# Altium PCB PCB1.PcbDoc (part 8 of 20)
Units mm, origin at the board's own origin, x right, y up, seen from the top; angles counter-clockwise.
Board outline 294.51 x 138.18 mm, 12 copper layers (Top Layer 1 _Signal, L2_GND, L3_Signals, L4_GND, L5_POWER, L6_Signals, L7_GND, L8_Signals, L9_GND, L10_POWER, L11_GND, Bottom Layer_Signals), stack 1.788 mm thick; 1254 components, 836 nets, 5699 pads, 2073 vias.
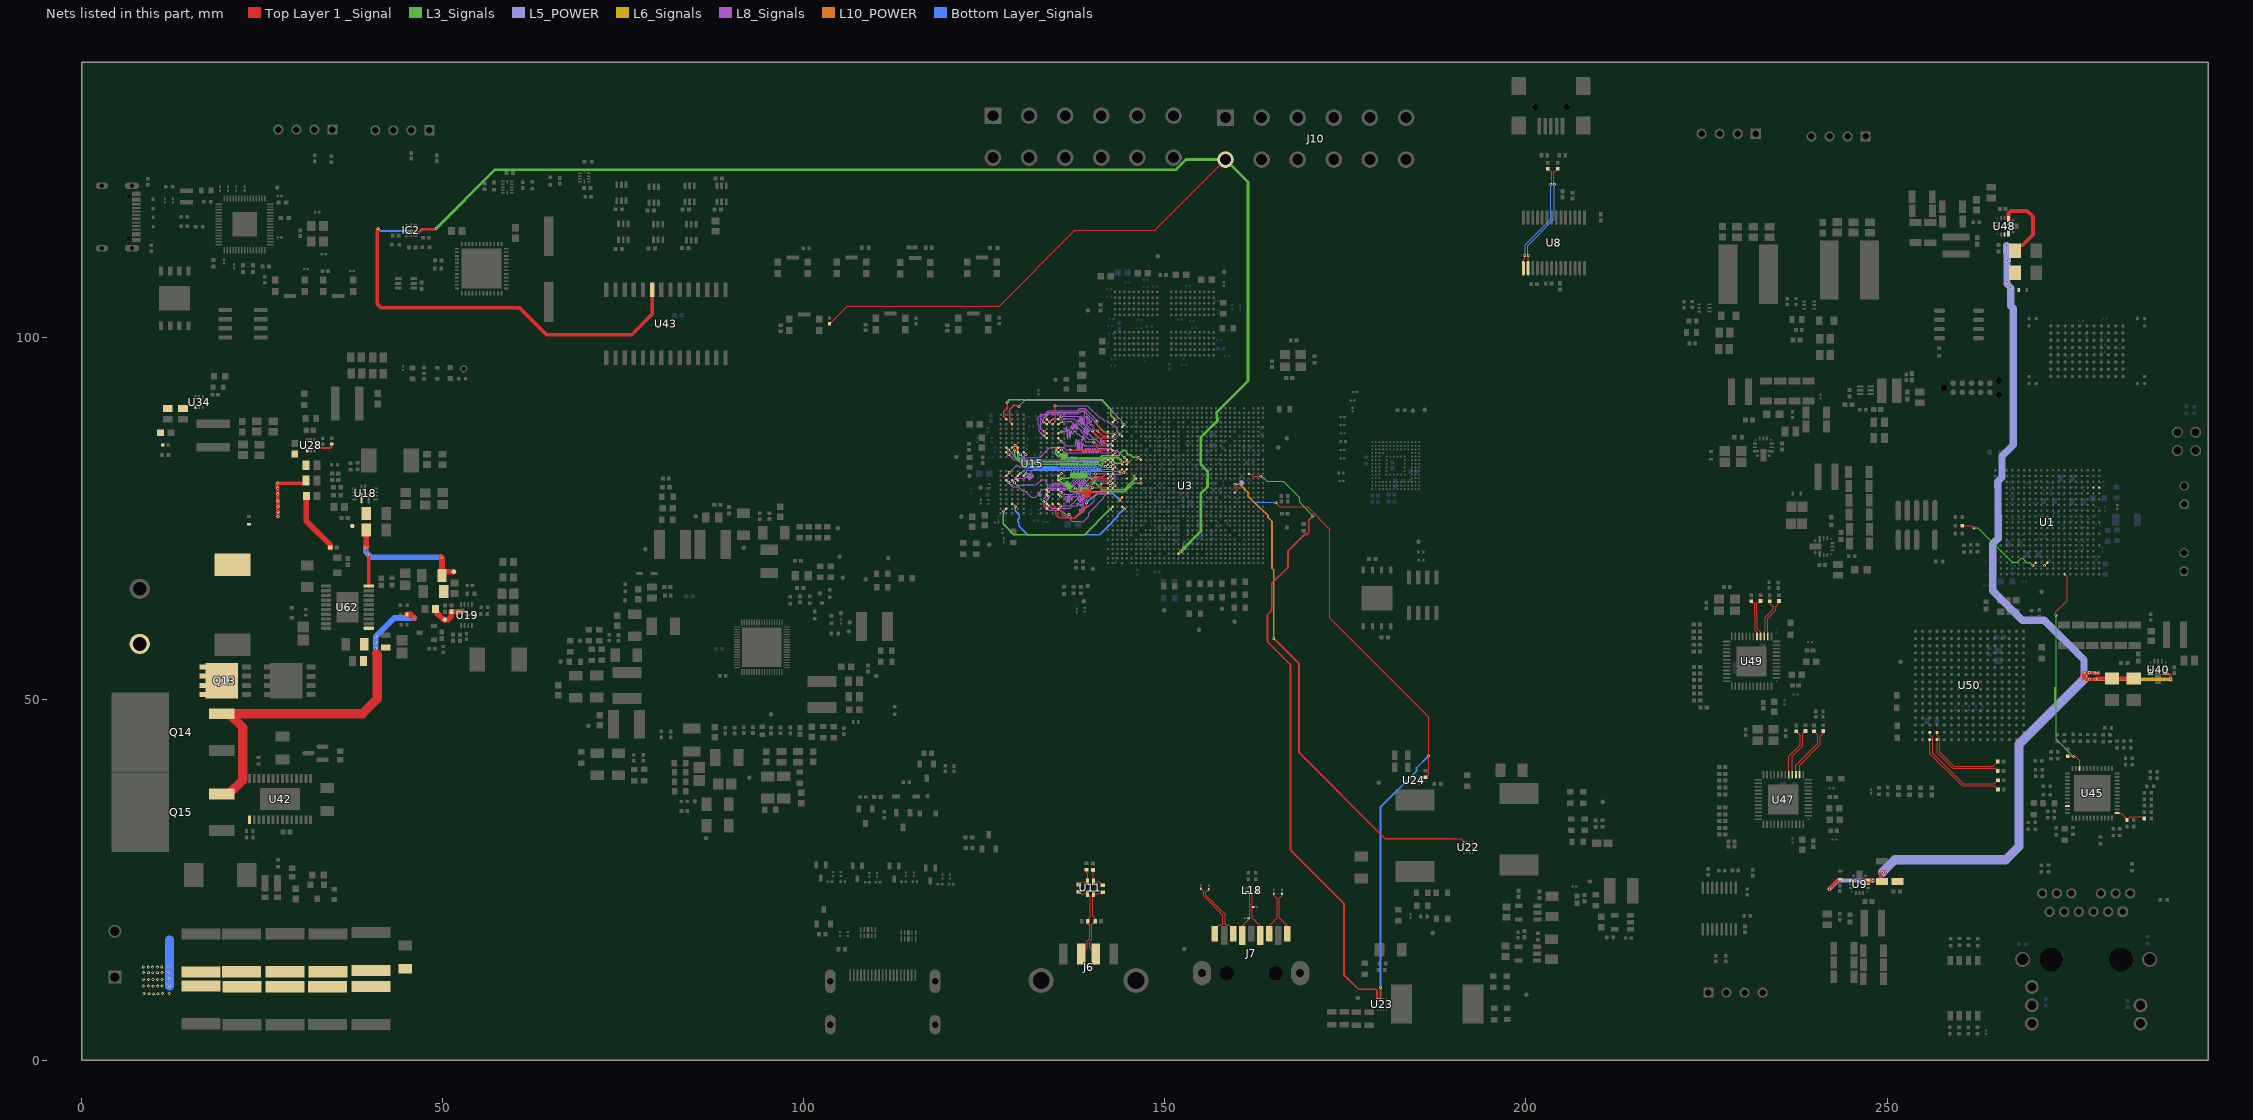
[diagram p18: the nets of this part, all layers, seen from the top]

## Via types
v1: diameter 0.4, hole 0.2, Top Layer 1 _Signal to Bottom Layer_Signals, 2009 vias
v2: diameter 0.508, hole 0.254, Top Layer 1 _Signal to Bottom Layer_Signals, 36 vias
v3: diameter 0.5, hole 0.2, Top Layer 1 _Signal to Bottom Layer_Signals, 12 vias
v4: diameter 1.27, hole 0.711, Top Layer 1 _Signal to Bottom Layer_Signals, 6 vias
v5: diameter 0.3, hole 0.2, Top Layer 1 _Signal to Bottom Layer_Signals, 5 vias
v6: diameter 0.254, hole 0.2, Top Layer 1 _Signal to Bottom Layer_Signals, 3 vias
v7: diameter 0.305, hole 0.2, Top Layer 1 _Signal to Bottom Layer_Signals, 1 vias
v8: diameter 0.254, hole 0.152, Top Layer 1 _Signal to Bottom Layer_Signals, 1 vias

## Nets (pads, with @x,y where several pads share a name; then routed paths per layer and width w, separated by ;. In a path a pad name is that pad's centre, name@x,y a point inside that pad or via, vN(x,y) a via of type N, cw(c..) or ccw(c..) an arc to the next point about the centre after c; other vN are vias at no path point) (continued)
12V: 1.2 2.2 3.2 4.2 C20.1 C21.1 C22.1 C184.2 C185.2 C187.1 C188.1 C189.1 C198.2 C321.1 C326.1 C329.1 C435.2 C492.1 C528.1 C529.2 C530.2 L29.2 R55.2 R81.2 R146.2 R296.2 TP16.1 TP65.1 TP66.1 U9.7 U9.8 U9.12 U18.1 U19.1 U28.1 U34.1 U40.7 U40.8 U40.12 U48.7 U48.8 U48.12 U62.10 | length 210.3
  Top Layer 1 _Signal w0.254: U28.1@31.237,84.371 31.26,84.394 31.26,84.592 31.5,84.832 32.474,84.832 32.563,84.743 34.435,84.743 34.635,84.944 R55.2@34.635,85.305
  Top Layer 1 _Signal w0.3: U40.12@288.553,53.474 288.578,53.449 289.093,53.449 289.268,53.274 289.268,53.215 289.282,53.202 v1(289.282,52.71)
  Top Layer 1 _Signal w0.508: v1(27.207,75.285) 27.184,75.308 v1(27.184,75.9) 27.184,76.645 v1(27.199,76.66) 27.207,76.667 v1(27.207,77.458) 27.165,77.499 v1(27.165,78.374) 27.151,78.388 v1(27.151,79.202) 27.136,79.217 v1(27.136,79.898) 30.866,79.898 31.087,80.119 C326.1@31.087,80.272 ; U62.10@39.768,65.636 39.768,69.729 ; v1(242.032,23.677) 242.032,23.792 243.225,24.986 243.49,24.986 243.522,25.018 C187.1@243.522,25.054 ; U9.8@247.213,24.888 247.235,24.867 v1(248.064,24.867) ; C188.1@249.309,24.727 249.143,24.892 249.143,25.805 v1(249.355,26.017) v1(249.901,26.017) ; U48.12@266.819,116.49 266.819,117.235 267.162,117.578 269.41,117.578 270.202,116.786 270.202,114.297 268.742,112.837 268.285,112.837 267.712,112.264 C530.2@267.712,112.089 ; v1(279.304,53.603) 279.288,53.588 v1(278.785,53.588) 278.722,53.651 v1(277.999,53.651) 277.942,53.593 v1(277.256,53.593) 277.256,52.734 v1(277.271,52.718) 277.287,52.734 v1(277.994,52.734) v1(278.927,52.734) 279.036,52.843 C185.2@284.186,52.843
  Top Layer 1 _Signal w0.762: C435.2@31.124,78.123 31.124,74.617 34.444,71.297 R296.2@34.444,70.966 ; v1(39.406,70.945) 1.2@39.406,73.389 ; C198.2@49.015,62.464 49.109,62.37 49.109,62.014 50.13,60.993 50.762,60.993 51.208,61.44 R81.2@51.208,62.094 52.699,62.094 U19.1@52.738,62.133 ; v1(49.819,69.618) 49.905,69.533 4.2@49.905,67.089 49.905,67.339 50.174,67.608 51.519,67.608 TP16.1@51.546,67.634
  L5_POWER w0.508: v1(242.032,23.677) 243.222,24.867 v1(248.064,24.867)
  L5_POWER w1.016: v1(266.532,111.871) 266.559,111.898 v1(266.559,112.753) 266.662,112.651 v1(266.662,110.674) 266.614,110.626 v1(266.614,107.759) 266.614,107.465 v1(267.154,106.925) 267.136,106.907 267.136,104.419 267.455,104.1 267.455,85.171 265.913,83.63 265.913,80.701 265.339,80.126 265.339,79.47 265.358,79.451 265.358,75.39 265.388,75.36 265.388,73.24 265.392,73.235 265.392,72.241 264.66,71.509 264.66,64.978 268.72,60.918 271.776,60.918 277.271,55.423 v1(277.271,52.718)
  L5_POWER w1.27: v1(249.355,26.017) 251.081,27.743 266.439,27.743 268.261,29.565 268.261,43.708 v1(277.271,52.718)
  L6_Signals w0.508: v1(278.927,52.734) 289.258,52.734 v1(289.282,52.71)
  Bottom Layer_Signals w0.762: 39.463,71.167 39.374,71.078 39.374,70.368 40.123,69.618 v1(49.819,69.618)
  other v1: 39.576,69.972
+24V: C39.1 C40.1 C575.2 C576.2 C577.2 C578.2 C579.2 C580.2 C581.2 C582.2 C583.2 C584.2 C585.2 CN1.2 Q13.5 Q13.6 Q13.7 Q13.8 Q14.3 Q15.3 R294.2 R295.2 U42.1 U62.1 | length 58.9
  Top Layer 1 _Signal w0.8: R295.2@45.053,61.694 45.568,61.694 v1(46.028,61.233)
  Top Layer 1 _Signal w1.27: Q15.3@19.417,36.857 20.417,36.857 22.304,38.744 22.304,46.07 20.417,47.956 Q14.3@19.417,47.956 38.884,47.956 40.941,50.014 40.941,56.136 40.816,56.262
  Bottom Layer_Signals w0.8: v1(40.741,56.979) v1(40.741,57.834) v1(40.741,58.667) 43.307,61.233 v1(46.028,61.233)
  Bottom Layer_Signals w1.27: v1(12.157,10.281) 12.157,16.611
  other v1: 9.329,9.181 9.938,9.177 8.63,9.203 10.581,9.19 11.19,9.199 12.198,9.224 9.288,10.238 9.897,10.234 10.54,10.247 8.589,10.259 11.149,10.255 9.877,11.162 8.569,11.187 9.268,11.166 10.52,11.174 11.129,11.183 12.137,11.209 9.247,12.094 9.856,12.089 10.5,12.102 8.548,12.115 11.109,12.111 12.117,12.137 9.234,12.879 9.843,12.875 10.486,12.888 8.535,12.901 11.095,12.897 12.103,12.922
_FIBRI0_N: C593.2 U47.14 | length 7.4
  Top Layer 1 _Signal w0.111: U47.14@237.887,39.535 237.887,40.845 240.775,43.733 240.775,44.842 241.181,45.248 C593.2@241.181,45.563
_FIBRI0_P: C594.2 U47.15 | length 7.5
  Top Layer 1 _Signal w0.111: U47.15@237.388,39.535 237.388,40.825 240.436,43.874 240.436,45.011 C594.2@239.897,45.55
_FIBRI1_N: C607.2 U49.14 | length 5.6
  Top Layer 1 _Signal w0.111: U49.14@233.491,58.655 233.491,59.239 233.486,59.244 233.486,61.187 234.559,62.261 234.559,62.78 235.032,63.252 C607.2@235.032,63.568
_FIBRI1_P: C608.2 U49.15 | length 5.6
  Top Layer 1 _Signal w0.111: U49.15@232.991,58.655 232.991,59.239 233.146,59.395 233.146,61.328 234.22,62.402 234.22,62.76 233.748,63.233 C608.2@233.748,63.548
_FIBRO0_N: C596.2 U47.17 | length 6.9
  Top Layer 1 _Signal w0.111: U47.17@236.388,39.535 236.388,42.058 238.003,43.674 238.003,44.983 237.493,45.494 237.485,45.494 C596.2@237.429,45.55
_FIBRO0_P: C595.2 U47.16 | length 6.8
  Top Layer 1 _Signal w0.111: U47.16@236.887,39.535 236.887,42.078 238.343,43.533 238.343,45.204 C595.2@238.705,45.566
_FIBRO1_N: C610.2 U49.17 | length 5.4
  Top Layer 1 _Signal w0.111: C610.2@231.188,63.549 231.382,63.356 231.634,63.356 231.699,63.291 231.699,61.585 231.757,61.526 231.757,59.473 231.991,59.239 U49.17@231.991,58.655
_FIBRO1_P: C609.2 U49.16 | length 5.5
  Top Layer 1 _Signal w0.111: C609.2@232.468,63.56 232.263,63.356 232.027,63.356 231.962,63.291 231.962,61.694 232.02,61.635 232.02,59.71 232.491,59.239 U49.16@232.491,58.655
_RD0_VS_N: C634.1 U50.P16 | length 13.4
  Top Layer 1 _Signal w0.161: U50.P16@255.919,44.379 255.922,44.376 255.922,42.448 260.411,37.959 264.871,37.959 C634.1@265.348,37.482
_RD0_VS_P: C633.1 U50.P15 | length 14
  Top Layer 1 _Signal w0.161: U50.P15@255.919,45.379 255.919,45.081 256.331,44.669 256.331,42.483 260.541,38.273 264.871,38.273 C633.1@265.348,38.75
_TD0_VS_N: C631.1 U50.N16 | length 11.3
  Top Layer 1 _Signal w0.161: U50.N16@256.919,44.379 256.972,44.327 256.972,44.164 256.988,44.147 256.988,42.515 257.08,42.423 259.101,40.402 264.958,40.402 C631.1@265.342,40.018
_TD0_VS_P: C630.1 U50.N15 | length 12
  Top Layer 1 _Signal w0.161: U50.N15@256.919,45.379 256.919,44.92 257.302,44.538 257.302,42.645 259.231,40.715 264.709,40.715 C630.1@265.326,41.332
_TYPEC0_OTG_D_N: J7.2 L18.2 R92.2 | length 6.9
  Top Layer 1 _Signal w0.131: J7.2@160.691,17.262 160.691,18.627 161.662,19.599 161.786,19.723 161.786,20.481 161.786,20.798 161.8,20.798 161.8,20.955 161.761,20.955 161.761,21.112 161.812,21.112 161.812,21.268 161.761,21.268 161.761,21.425 161.812,21.425 161.812,21.582 161.786,21.582 161.786,21.647 161.786,23.01 161.595,23.201 161.507,23.201 L18.2@161.441,23.267
_TYPEC0_OTG_D_P: J7.3 L18.3 R95.2 | length 6.9
  Top Layer 1 _Signal w0.131: L18.3@162.666,23.267 162.601,23.201 162.287,23.201 162.096,23.01 162.096,19.723 163.191,18.627 J7.3@163.191,17.262
_TYPEC0_SSRX1_N: J7.5 R96.2 | length 6.2
  Top Layer 1 _Signal w0.131: R96.2@166.233,23.047 166.233,22.805 165.846,22.417 165.846,19.723 166.941,18.627 J7.5@166.941,17.487
_TYPEC0_SSRX1_P: J7.6 R97.2 | length 6.2
  Top Layer 1 _Signal w0.131: J7.6@164.441,17.487 164.441,18.627 165.536,19.723 165.536,22.353 165.076,22.813 R97.2@165.076,23.056
_TYPEC0_SSTX1_N: C457.2 J7.8 | length 8.2
  Top Layer 1 _Signal w0.131: C457.2@156.081,23.673 155.677,23.269 155.677,22.852 156.312,22.217 156.358,22.171 157.216,21.313 157.231,21.327 157.341,21.216 157.309,21.184 157.42,21.073 157.438,21.091 157.484,21.045 158.345,20.184 158.345,18.788 158.422,18.711 158.841,18.711 159.441,18.112 J7.8@159.441,17.487
_TYPEC0_SSTX1_P: C458.2 J7.9 | length 8.2
  Top Layer 1 _Signal w0.131: C458.2@154.964,23.719 155.368,23.315 155.368,22.724 158.036,20.056 158.036,18.788 157.959,18.711 157.54,18.711 156.941,18.112 J7.9@156.941,17.487
_TYPEC1_OTG__D_N: J6.2 R74.2 U11.2 U13.2 | length 10.6
  Top Layer 1 _Signal w0.131: R74.2@138.098,23.312 138.148,23.312 138.431,23.029 U11.2@139.302,23.029 139.685,22.646 139.685,22.206 139.685,19.847 139.474,19.636 139.474,19.391 U13.2@139.314,19.231 139.314,18.865 139.601,18.578 139.601,16.791 139.272,16.462 139.272,15.542 J6.2@138.427,14.697
_TYPEC1_OTG__D_P: J6.3 R175.2 U11.3 U14.2 | length 10.6
  Top Layer 1 _Signal w0.131: J6.3@140.427,14.697 139.581,15.542 139.581,16.334 139.91,16.663 139.91,18.768 U14.2@140.365,19.222 140.365,19.588 139.994,19.959 139.994,22.405 140.048,22.459 140.048,22.974 U11.3@140.102,23.029 141.175,23.029 141.368,23.221 R175.2@141.418,23.221
_TYPEC1_OTG_D_N: R74.1 R173.2 U11.1 | length 3.1
  Top Layer 1 _Signal w0.131: R74.1@138.098,24.312 138.148,24.312 138.565,24.729 U11.1@139.302,24.729 139.302,25.857 139.133,26.026 R173.2@139.133,26.342
_TYPEC1_OTG_D_P: R174.2 R175.1 U11.4 | length 3.1
  Top Layer 1 _Signal w0.131: R174.2@140.079,26.325 140.079,25.268 140.102,25.244 U11.4@140.102,24.729 140.861,24.729 141.368,24.221 R175.1@141.418,24.221
_USB__N: R166.1 U8.16 | length 15.6
  Top Layer 1 _Signal w0.161: U8.16@200.291,109.664 200.291,111.398 v1(200.322,111.428) ; v1(203.94,121.278) 203.855,121.363 203.855,122.91 R166.1@204.376,123.43
  Bottom Layer_Signals w0.161: v1(200.322,111.428) 200.237,111.513 200.237,112.769 203.94,116.472 v1(203.94,121.278)
_USB__P: R167.1 U8.15 | length 15.6
  Top Layer 1 _Signal w0.161: U8.15@199.641,109.664 199.641,110.744 199.838,110.941 v1(199.838,111.428) ; R167.1@203.02,123.45 203.541,122.93 203.541,121.363 v1(203.456,121.278)
  Bottom Layer_Signals w0.161: v1(199.838,111.428) 199.923,111.513 199.923,112.899 203.456,116.432 v1(203.456,121.278)
ALLPHYAD: R393.1 R394.2 U45.13 | length 4.6
  Top Layer 1 _Signal w0.152: U45.13@281.874,34.203 282.426,34.203 283.076,33.554 283.076,33.388 R393.1@283.225,33.239 283.225,33.255 283.684,33.715 285.402,33.715 285.642,33.474 R394.2@285.642,33.459
BIG/NPU_EN: R122.1 R123.2 U23.A2 U24.A2 | length 93.1
  Top Layer 1 _Signal w0.161: v1(165.373,77.183) 165.923,76.633 169.756,76.633 172.85,73.538 172.85,61.157 186.52,47.487 186.52,42.123 v1(186.483,42.086) 186.52,42.048 186.52,39.595 186.106,39.18 185.564,39.18 185.449,39.066 185.366,39.066 185.258,38.957 U24.A2@185.247,38.957
  Top Layer 1 _Signal w0.254: U23.A2@179.853,8.514 v1(179.853,10.065)
  Bottom Layer_Signals w0.161: R122.1@160.596,79.938 160.439,79.781 160.439,79.756 160.719,79.475 160.719,79.301 160.763,79.257 160.817,79.257 161.531,78.542 161.531,78.024 162.246,77.31 162.36,77.31 162.431,77.239 165.317,77.239 v1(165.373,77.183)
  Bottom Layer_Signals w0.254: v1(179.853,10.065) 179.853,35.016 184.848,40.011 184.848,40.452 v1(186.483,42.086)
BOOT_SARADC_IN0: IC2.10 U43.23 | length 60.3
  Top Layer 1 _Signal w0.254: IC2.10@45.042,114.493 45.069,114.52 45.371,114.52 45.569,114.718 45.572,114.718 v1(45.667,114.813)
  Top Layer 1 _Signal w0.508: v1(41.027,115.112) 41.027,115.029 40.961,114.963 40.961,104.684 41.47,104.175 60.639,104.175 64.361,100.453 76.18,100.453 78.998,103.272 U43.23@78.998,106.647
  Bottom Layer_Signals w0.254: v1(41.027,115.112) 41.066,115.112 41.365,114.813 v1(45.667,114.813)
BOOT_SARADC_IN0_: IC2.2 J10.7 R130.2 R183.1 U3.AM16 | length 242
  Top Layer 1 _Signal w0.132: R183.1@103.568,101.959 103.572,101.959 106.029,104.416 127.065,104.416 137.538,114.888 148.58,114.888 J10.7@158.395,124.704
  Top Layer 1 _Signal w0.381: IC2.2@46.242,114.493 46.268,114.519 46.606,114.519 47.142,115.055 49.026,115.055 v1(49.105,115.134) ; U3.AM16@151.879,70.128 151.897,70.128 152.222,70.453 v1(152.227,70.453)
  L3_Signals w0.381: v1(49.105,115.134) 57.272,123.301 151.541,123.301 152.944,124.704 J10.7@158.395,124.704 161.5,121.599 161.5,94.025 157.199,89.725 157.199,89.014 157.285,88.928 157.285,88.535 155.628,86.879 155.606,86.879 154.988,86.26 154.988,85.867 154.979,85.859 154.979,82.45 155.931,81.498 155.931,80.422 155.907,80.398 155.907,79.377 154.963,78.432 154.963,73.173 152.246,70.457 152.236,70.457 v1@152.236,70.453
  Bottom Layer_Signals w0.381: v1(152.227,70.453) 152.231,70.457 152.279,70.457 152.673,70.851 R130.2@152.673,70.894
CK_LAN25: U1.K17 | length 0.6
  Top Layer 1 _Signal w0.132: v1(271.806,68.461) 271.806,68.483 272.159,68.836 272.181,68.836 U1.K17@272.181,68.88
CK_LAN_N: U1.A4
CK_LAN_P: U1.B4
CK_RPHY25: U45.46
CLK125EN: R396.2 U1.G19 U45.34 | length 34
  Top Layer 1 _Signal w0.132: v1(273.374,61.579) 273.374,62.069 274.923,63.618 274.923,66.938 U1.G19@274.581,67.28 ; R396.2@275.041,42.102 275.083,42.06 275.812,42.06 275.815,42.057 276.071,42.057 276.674,41.453 U45.34@276.674,40.403
  L3_Signals w0.113: v1(273.374,61.579) 273.418,61.535 273.418,51.849 273.418,51.792 273.443,51.792 273.443,51.655 273.223,51.655 273.223,51.517 273.443,51.517 273.443,51.379 273.223,51.379 273.223,51.241 273.443,51.241 273.443,51.103 273.223,51.103 273.223,50.965 273.443,50.965 273.443,50.827 273.223,50.827 273.223,50.689 273.443,50.689 273.443,50.551 273.223,50.551 273.223,50.413 273.443,50.413 273.443,50.275 273.223,50.275 273.223,50.137 273.443,50.137 273.443,50 273.223,50 273.223,49.862 273.443,49.862 273.443,49.724 273.223,49.724 273.223,49.586 273.443,49.586 273.443,49.448 273.223,49.448 273.223,49.31 273.443,49.31 273.443,49.172 273.418,49.172 273.418,49.09 273.418,44.416 v1(275.815,42.019)
CPU_BIG0_VSEL: U3.R31 U23.A1 | length 89.1
  Top Layer 1 _Signal w0.152: U3.R31@161.629,81.178 161.633,81.174 161.87,81.174 161.959,81.085 161.959,81.045 162.152,80.853 v1(163.277,80.853)
  Top Layer 1 _Signal w0.254: v1(170.512,75.361) 169.915,74.763 169.915,73.035 169.646,72.766 169.32,72.766 167.063,70.509 167.063,68.281 164.806,66.024 164.806,62.269 164.214,61.677 164.214,57.946 167.379,54.782 167.379,29.113 174.79,21.702 174.79,11.836 176.813,9.813 179.215,9.813 179.364,9.664 179.364,8.603 U23.A1@179.453,8.514
  L3_Signals w0.152: v1(163.277,80.853) 163.324,80.806 163.539,80.806 164.2,80.144 166.378,80.144 168.657,77.865 168.657,77.216 v1(170.512,75.361)
CPU_BIG1_VSEL: U3.W28 U22.A1 | length 70.6
  Top Layer 1 _Signal w0.161: U3.W28@159.679,78.578 160.004,78.902 160.004,79.414 159.712,79.706 v1(159.712,79.746) ; 190.136,30.655 191.005,30.655 U22.A1@191.399,30.261
  Top Layer 1 _Signal w0.254: v1(165.08,58.395) 168.582,54.893 168.582,42.559 180.487,30.655 190.136,30.655
  L10_POWER w0.254: v1(159.712,79.746) 160.339,79.746 160.783,79.303 160.836,79.303 161.077,79.062 161.077,79.009 161.55,78.535 161.55,78.053 162.412,77.192 162.455,77.192 164.29,75.357 164.29,75.133 164.835,74.588 164.835,68.08 165.08,67.836 v1(165.08,58.395)
CPU_nRST: R11.2 U1.M17 | length 13.1
  Top Layer 1 _Signal w0.132: v1(270.197,68.496) U1.M17@270.581,68.88
  Top Layer 1 _Signal w0.161: R11.2@260.419,74.01 261.691,74.01 v1(262.011,73.69)
  L3_Signals w0.161: v1(262.011,73.69) 262.594,73.69 267.32,68.963 268.035,68.963 268.572,69.5 268.784,69.5 269.06,69.223 269.06,69.145 269.337,68.868 269.825,68.868 v1(270.197,68.496)
DDR_CH0_A0_A: U3.T7 U15.H2 | length 21.8
  Top Layer 1 _Signal w0.203: U15.H2@135.25,80.271 135.29,80.271 135.525,80.506 135.61,80.506 v1(135.648,80.543) ; v1(145.724,80.854) 145.724,80.844 146.029,80.539 U3.T7@146.029,80.528
  L3_Signals w0.179: v1(135.648,80.543) 136.62,80.543 136.698,80.621 136.787,80.621 ccw(c136.787,80.8) 136.967,80.8 136.967,81.194 cw(c137.069,81.194) 137.171,81.194 137.171,80.698 ccw(c137.274,80.698) 137.376,80.698 137.376,81.194 cw(c137.478,81.194) 137.581,81.194 137.581,80.698 ccw(c137.683,80.698) 137.785,80.698 137.785,81.194 cw(c137.888,81.194) 137.99,81.194 137.99,80.698 ccw(c138.093,80.698) 138.195,80.698 138.195,81.194 cw(c138.297,81.194) 138.4,81.194 138.4,80.698 ccw(c138.502,80.698) 138.604,80.698 138.604,81.194 cw(c138.707,81.194) 138.809,81.194 138.809,80.698 ccw(c138.911,80.698) 139.014,80.698 139.014,81.194 cw(c139.116,81.194) 139.219,81.194 139.219,80.8 ccw(c139.398,80.8) 139.398,80.621 139.669,80.621 139.698,80.621 139.801,80.519 139.864,80.455 ccw(c139.991,80.582) 140.118,80.455 140.381,80.718 cw(c140.467,80.632) 140.553,80.718 cw(c140.467,80.632) 140.553,80.546 139.983,79.976 ccw(c140.069,79.89) 139.983,79.804 ccw(c140.069,79.89) 140.155,79.804 140.208,79.857 cw(c140.335,79.731) 140.462,79.857 140.783,79.536 140.847,79.473 141.339,78.98 144.36,78.98 145.226,79.846 145.247,79.846 145.466,80.065 145.466,80.086 145.731,80.351 145.731,80.848 v1(145.724,80.854)
DDR_CH0_A0_B: U3.M8 U15.R2 | length 17.8
  Top Layer 1 _Signal w0.203: v1(134.919,84.51) 134.929,84.51 135.24,84.821 U15.R2@135.25,84.821 ; v1(146.354,83.444) 146.358,83.444 146.675,83.128 U3.M8@146.679,83.128
  L3_Signals w0.179: v1(134.919,84.51) 134.919,83.894 135.013,83.799 135.156,83.657 ccw(c135.282,83.784) 135.462,83.784 135.462,83.857 cw(c135.564,83.857) 135.666,83.857 135.666,83.247 ccw(c135.769,83.247) 135.871,83.247 135.871,83.857 cw(c135.973,83.857) 136.076,83.857 136.076,83.247 ccw(c136.178,83.247) 136.281,83.247 136.281,83.834 cw(c136.383,83.834) 136.485,83.834 136.485,83.532 ccw(c136.665,83.532) 136.665,83.352 137.043,83.352 140.983,83.352 141.329,83.698 143.673,83.698 143.778,83.803 143.778,84.023 144.206,84.45 144.515,84.45 144.734,84.232 144.734,84.015 144.922,83.826 145.232,83.826 145.614,83.444 v1(146.354,83.444)
DDR_CH0_A1_A: U3.T8 U15.J2 | length 22
  Top Layer 1 _Signal w0.203: U15.J2@135.25,80.921 135.29,80.921 135.552,81.183 135.637,81.183 v1(135.675,81.22) ; U3.T8@146.679,80.528 146.688,80.52 146.688,79.883 v1(146.696,79.875)
  L3_Signals w0.179: v1(135.675,81.22) 135.193,80.738 135.193,80.47 135.577,80.086 135.629,80.086 135.692,80.023 135.886,79.829 ccw(c136.013,79.956) 136.14,79.829 136.417,80.106 cw(c136.489,80.034) 136.561,80.106 cw(c136.489,80.034) 136.561,79.961 136.212,79.612 ccw(c136.284,79.54) 136.212,79.467 ccw(c136.284,79.54) 136.357,79.467 136.706,79.817 cw(c136.779,79.744) 136.851,79.817 cw(c136.779,79.744) 136.851,79.672 136.502,79.323 ccw(c136.574,79.25) 136.502,79.178 ccw(c136.574,79.25) 136.646,79.178 136.996,79.527 cw(c137.068,79.455) 137.141,79.527 cw(c137.068,79.455) 137.141,79.382 136.864,79.105 ccw(c136.99,78.979) 136.864,78.852 137.008,78.707 137.014,78.701 137.129,78.701 137.383,78.701 137.762,78.701 ccw(c137.762,78.881) 137.942,78.881 137.942,78.954 cw(c138.044,78.954) 138.146,78.954 138.146,78.778 ccw(c138.249,78.778) 138.351,78.778 138.351,79.183 cw(c138.453,79.183) 138.556,79.183 138.556,78.778 ccw(c138.658,78.778) 138.761,78.778 138.761,79.183 cw(c138.863,79.183) 138.965,79.183 138.965,78.778 ccw(c139.068,78.778) 139.17,78.778 139.17,79.165 cw(c139.272,79.165) 139.375,79.165 139.375,78.881 ccw(c139.554,78.881) 139.554,78.701 140.667,78.701 144.453,78.701 145.335,79.583 145.356,79.583 145.681,79.908 146.663,79.908 v1(146.696,79.875)
DDR_CH0_A1_B: U3.M5 U15.P2 | length 17.5
  Top Layer 1 _Signal w0.203: U15.P2@135.25,84.171 135.29,84.171 135.592,84.473 135.653,84.473 v1(135.69,84.511) ; v1(144.38,83.427) 144.399,83.427 144.698,83.128 U3.M5@144.729,83.128
  L8_Signals w0.135: v1(135.69,84.511) 136.109,84.092 138.434,84.092 138.501,84.092 ccw(c138.501,84.227) 138.636,84.227 138.636,84.236 cw(c138.716,84.236) 138.796,84.236 138.796,84.147 ccw(c138.876,84.147) 138.956,84.147 138.956,84.584 cw(c139.037,84.584) 139.117,84.584 139.117,84.147 ccw(c139.197,84.147) 139.277,84.147 139.277,84.584 cw(c139.357,84.584) 139.437,84.584 139.437,84.147 ccw(c139.517,84.147) 139.598,84.147 139.598,84.584 cw(c139.678,84.584) 139.758,84.584 139.758,84.147 ccw(c139.838,84.147) 139.918,84.147 139.918,84.584 cw(c139.998,84.584) 140.078,84.584 140.078,84.147 ccw(c140.159,84.147) 140.239,84.147 140.239,84.584 cw(c140.319,84.584) 140.399,84.584 140.399,84.147 ccw(c140.479,84.147) 140.559,84.147 140.559,84.423 cw(c140.639,84.423) 140.72,84.423 140.72,84.147 ccw(c140.8,84.147) 140.88,84.147 140.88,84.419 cw(c140.96,84.419) 141.04,84.419 141.04,84.227 ccw(c141.175,84.227) 141.175,84.092 141.561,84.092 142.516,84.092 142.88,84.457 143.35,84.457 v1(144.38,83.427)
DDR_CH0_A2_A: U3.P4 U15.H9 | length 19.6
  Top Layer 1 _Signal w0.203: v1(129.355,80.562) 129.357,80.562 U15.H9@129.65,80.271 U15.H9@129.65,80.271 ; v1@143.739,81.52 143.739,81.51 143.751,81.51 144.068,81.828 U3.P4@144.079,81.828 U3.P4@144.048,81.828
  L8_Signals w0.135: v1(129.355,80.562) 129.378,80.539 130.565,80.539 130.726,80.7 cw(c130.822,80.605) 130.917,80.7 131.235,80.382 ccw(c131.292,80.438) 131.348,80.382 ccw(c131.292,80.438) 131.348,80.495 130.992,80.852 cw(c131.048,80.909) 130.992,80.965 cw(c131.048,80.909) 131.105,80.965 131.462,80.608 ccw(c131.518,80.665) 131.575,80.608 ccw(c131.518,80.665) 131.575,80.722 131.2,81.097 cw(c131.257,81.153) 131.2,81.21 cw(c131.257,81.153) 131.314,81.21 131.688,80.835 ccw(c131.745,80.892) 131.802,80.835 ccw(c131.745,80.892) 131.802,80.948 131.484,81.267 cw(c131.579,81.362) 131.484,81.457 131.746,81.72 131.846,81.82 142.314,81.82 142.32,81.813 142.719,81.813 143.022,81.51 v1@143.739,81.51
  other v1: 143.823,81.457
DDR_CH0_A2_B: U3.N5 U15.R9 | length 19.6
  Top Layer 1 _Signal w0.203: v1(129.188,84.494) 129.225,84.531 129.321,84.531 129.61,84.821 U15.R9@129.65,84.821 ; U3.N5@144.729,82.478 144.765,82.513 144.77,82.513 145.087,82.829 145.087,82.871 v6(145.096,82.881)
  L3_Signals w0.179: v1(129.188,84.494) 129.188,83.572 130.236,82.524 140.877,82.524 141.127,82.274 141.275,82.274 141.38,82.379 141.38,82.592 141.328,82.644 141.328,82.953 141.547,83.172 142.607,83.172 143.151,82.628 144.073,82.628 144.326,82.881 v6(145.096,82.881)
DDR_CH0_A3_A: U3.P5 U15.H10 | length 19.6
  Top Layer 1 _Signal w0.203: U15.H10@128.85,80.271 v1(129.177,79.944) ; v1(144.32,81.353) 144.32,81.387 144.729,81.796 U3.P5@144.729,81.828
  L8_Signals w0.135: v1(129.177,79.944) 129.494,79.627 129.797,79.627 129.823,79.601 130.114,79.601 130.18,79.667 132.206,79.667 132.92,80.382 133.405,80.382 133.61,80.176 133.61,79.885 133.731,79.764 133.817,79.764 133.938,79.644 134.186,79.644 134.21,79.667 134.278,79.667 ccw(c134.278,79.802) 134.412,79.802 134.412,79.816 cw(c134.493,79.816) 134.573,79.816 134.573,79.725 ccw(c134.653,79.725) 134.733,79.725 134.733,79.816 cw(c134.813,79.816) 134.893,79.816 134.893,79.725 ccw(c134.973,79.725) 135.054,79.725 135.054,79.816 cw(c135.134,79.816) 135.214,79.816 135.214,79.725 ccw(c135.294,79.725) 135.374,79.725 135.374,79.816 cw(c135.454,79.816) 135.534,79.816 135.534,79.802 ccw(c135.669,79.802) 135.669,79.667 136.007,79.667 136.032,79.667 136.07,79.705 136.797,79.705 138.657,81.565 142.658,81.565 143.096,81.127 143.655,81.127 143.677,81.105 144,81.105 144.248,81.353 v1(144.32,81.353)
DDR_CH0_A3_B: U3.N4 U15.R10 | length 17.9
  Top Layer 1 _Signal w0.203: U15.R10@128.85,84.821 128.89,84.821 129.127,85.057 129.245,85.057 v1(129.282,85.095) ; v1(143.918,83.002) 143.918,82.948 144.057,82.81 144.057,82.5 U3.N4@144.079,82.478
  L3_Signals w0.179: v1(129.282,85.095) 129.608,84.769 129.608,83.54 130.267,82.881 140.884,82.881 141.438,83.435 143.577,83.435 143.81,83.202 143.81,83.17 143.918,83.061 v1(143.918,83.002)
DDR_CH0_A4_A: U3.R1 U15.H11 | length 18
  Top Layer 1 _Signal w0.203: U15.H11@128.05,80.271 128.074,80.271 128.38,79.965 v1(128.404,79.965) ; v1(140.396,81.178) U3.R1@142.129,81.178
  L8_Signals w0.135: v1(128.404,79.965) 128.404,79.897 128.893,79.408 129.707,79.408 130.137,78.977 130.146,78.977 130.352,78.771 130.658,78.771 131.187,78.242 131.187,78.203 131.477,77.913 132.069,77.913 132.327,78.172 132.327,78.208 132.327,78.236 132.415,78.323 132.684,78.053 132.798,78.167 132.349,78.616 132.462,78.729 132.706,78.485 132.819,78.599 132.755,78.663 132.802,78.711 132.819,78.728 132.819,78.76 133.025,78.966 133.058,78.966 133.126,79.035 133.437,79.035 133.828,79.426 133.846,79.426 133.847,79.425 134.301,79.425 134.302,79.426 136.1,79.426 136.161,79.487 136.814,79.487 136.87,79.431 136.982,79.431 138.729,81.178 v1(140.396,81.178)
DDR_CH0_A4_B: U3.K1 U15.R11 | length 15.5
  Top Layer 1 _Signal w0.203: U15.R11@128.05,84.821 128.05,84.781 128.123,84.707 128.123,84.693 128.303,84.513 128.358,84.513 v1(128.395,84.475) ; v1(136.849,84.473) 136.872,84.45 142.107,84.45 U3.K1@142.129,84.428
  L8_Signals w0.135: v1(128.395,84.475) 129.44,83.431 132.71,83.431 133.584,84.305 133.584,84.407 133.96,84.783 134.242,84.783 134.321,84.861 135.372,84.861 ; 135.373,84.862 135.967,84.862 136.356,84.473 v1(136.849,84.473)
DDR_CH0_A5_A: U3.P2 U15.J11 | length 17.7
  Top Layer 1 _Signal w0.203: U15.J11@128.05,80.921 128.05,80.933 128.45,81.333 v1(128.45,81.346) ; U3.P2@142.779,81.828 v1(143.092,82.14)
  L8_Signals w0.135: v1@128.399,81.177 128.399,81.295 129.188,82.084 129.193,82.084 129.389,82.281 129.68,82.281 129.877,82.084 140.726,82.084 141.351,82.709 141.351,82.965 141.587,83.201 142.628,83.201 143.092,82.737 v1(143.092,82.14)
DDR_CH0_A5_B: U3.L2 U15.P11 | length 16.4
  Top Layer 1 _Signal w0.203: U15.P11@128.05,84.171 128.382,83.839 v1@128.395,83.839 ; U3.L2@142.779,83.778 142.787,83.778 143.115,84.106 v1(143.123,84.106)
  L8_Signals w0.135: v1(128.4,83.819) 128.4,83.799 129.074,83.126 141.202,83.126 141.496,83.42 142.493,83.42 142.912,83.838 142.912,83.894 v1(143.123,84.106)
DDR_CH0_A6_A: U3.T5
DDR_CH0_CLK_A_N: U3.N1 U15.J9 | length 20.9
  Top Layer 1 _Signal w0.161: U15.J9@129.65,80.921 v1(129.951,81.222) ; v1(141.754,82.232) 141.883,82.232 U3.N1@142.129,82.478
  Bottom Layer_Signals w0.161: v1(129.951,81.222) 129.996,81.222 130.749,81.974 135.357,81.974 135.438,81.974 ccw(c135.438,82.135) 135.599,82.135 135.599,82.277 cw(c135.705,82.277) 135.811,82.277 135.811,82.08 ccw(c135.917,82.08) 136.023,82.08 136.023,82.277 cw(c136.129,82.277) 136.236,82.277 136.236,82.08 ccw(c136.342,82.08) 136.448,82.08 136.448,82.277 cw(c136.554,82.277) 136.66,82.277 136.66,82.08 ccw(c136.766,82.08) 136.872,82.08 136.872,82.277 cw(c136.978,82.277) 137.084,82.277 137.084,82.08 ccw(c137.19,82.08) 137.296,82.08 137.296,82.277 cw(c137.402,82.277) 137.508,82.277 137.508,82.077 ccw(c137.614,82.077) 137.72,82.077 137.72,82.277 cw(c137.826,82.277) 137.932,82.277 137.932,82.08 ccw(c138.038,82.08) 138.144,82.08 138.144,82.29 cw(c138.25,82.29) 138.356,82.29 138.356,82.077 ccw(c138.462,82.077) 138.568,82.077 138.568,82.287 cw(c138.675,82.287) 138.781,82.287 138.781,82.071 ccw(c138.887,82.071) 138.993,82.071 138.993,82.286 cw(c139.099,82.286) 139.205,82.286 139.205,82.066 ccw(c139.311,82.066) 139.417,82.066 139.417,82.286 cw(c139.523,82.286) 139.629,82.286 139.629,82.081 ccw(c139.735,82.081) 139.841,82.081 139.841,82.286 cw(c139.947,82.286) 140.053,82.286 140.053,82.08 ccw(c140.159,82.08) 140.265,82.08 140.265,82.279 cw(c140.371,82.279) 140.477,82.279 140.477,82.135 ccw(c140.639,82.135) 140.639,81.974 141,81.974 141.085,81.974 141.27,82.158 141.54,82.158 141.568,82.186 141.708,82.186 v1(141.754,82.232)
DDR_CH0_CLK_A_P: U3.N2 U15.J8 | length 21
  Top Layer 1 _Signal w0.161: U15.J8@130.45,80.921 v1(130.778,81.249) ; v1(142.466,82.164) U3.N2@142.779,82.478
  Bottom Layer_Signals w0.161: v1(130.778,81.249) 130.774,81.253 130.774,81.555 130.879,81.66 136.658,81.66 136.976,81.66 cw(c136.976,81.499) 137.137,81.499 137.137,80.818 ccw(c137.256,80.818) 137.375,80.818 137.375,81.538 cw(c137.494,81.538) 137.612,81.538 137.612,80.987 ccw(c137.731,80.987) 137.85,80.987 137.85,81.542 cw(c137.969,81.542) 138.087,81.542 138.087,80.987 ccw(c138.206,80.987) 138.325,80.987 138.325,81.539 cw(c138.444,81.539) 138.562,81.539 138.562,81.096 ccw(c138.681,81.096) 138.8,81.096 138.8,81.533 cw(c138.919,81.533) 139.037,81.533 139.037,81.094 ccw(c139.156,81.094) 139.275,81.094 139.275,81.528 cw(c139.394,81.528) 139.512,81.528 139.512,81.115 ccw(c139.631,81.115) 139.75,81.115 139.75,81.499 cw(c139.911,81.499) 139.911,81.66 140.424,81.66 141.215,81.66 141.4,81.845 141.882,81.845 142.156,82.119 142.42,82.119 v1(142.466,82.164)
DDR_CH0_CLK_B_N: U3.M1 U15.P9 | length 19.2
  Top Layer 1 _Signal w0.161: U15.P9@129.65,84.171 v1(129.997,83.823) ; v1(141.702,82.799) 142.001,83.098 142.099,83.098 U3.M1@142.129,83.128
  Bottom Layer_Signals w0.161: v1(129.997,83.823) 130.01,83.823 130.224,83.609 130.224,83.167 131.172,82.219 135.008,82.219 135.417,82.628 137.27,82.628 137.886,82.628 138.32,83.062 138.384,83.127 138.587,83.127 cw(c138.587,82.965) 138.748,82.965 138.748,82.729 ccw(c138.842,82.729) 138.935,82.729 138.935,83.033 cw(c139.028,83.033) 139.122,83.033 139.122,82.731 ccw(c139.215,82.731) 139.308,82.731 139.308,83.033 cw(c139.402,83.033) 139.495,83.033 139.495,82.731 ccw(c139.588,82.731) 139.682,82.731 139.682,83.033 cw(c139.775,83.033) 139.868,83.033 139.868,82.731 ccw(c139.962,82.731) 140.055,82.731 140.055,83.033 cw(c140.148,83.033) 140.242,83.033 140.242,82.731 ccw(c140.335,82.731) 140.428,82.731 140.428,83.033 cw(c140.522,83.033) 140.615,83.033 140.615,82.632 ccw(c140.708,82.632) 140.802,82.632 140.802,82.965 cw(c140.963,82.965) 140.963,83.127 141.258,83.127 141.374,83.127 v1(141.702,82.799)
DDR_CH0_CLK_B_P: U3.M2 U15.P8 | length 19.7
  Top Layer 1 _Signal w0.161: U15.P8@130.45,84.171 v1(130.765,83.856) ; v1(142.461,82.789) 142.461,82.8 142.779,83.117 U3.M2@142.779,83.128
  Bottom Layer_Signals w0.161: v1(130.765,83.856) 130.752,83.856 130.538,83.642 130.538,83.297 131.218,82.617 131.302,82.533 131.627,82.533 ccw(c131.627,82.694) 131.788,82.694 131.788,82.881 cw(c131.881,82.881) 131.975,82.881 131.975,82.626 ccw(c132.068,82.626) 132.161,82.626 132.161,82.873 cw(c132.255,82.873) 132.348,82.873 132.348,82.626 ccw(c132.441,82.626) 132.535,82.626 132.535,82.847 cw(c132.628,82.847) 132.722,82.847 132.722,82.694 ccw(c132.883,82.694) 132.883,82.533 133.15,82.533 134.878,82.533 135.287,82.942 136.087,82.942 136.38,82.942 ccw(c136.38,83.103) 136.541,83.103 136.541,83.306 cw(c136.632,83.306) 136.723,83.306 136.723,83.033 ccw(c136.814,83.033) 136.905,83.033 136.905,83.405 cw(c136.995,83.405) 137.086,83.405 137.086,83.033 ccw(c137.177,83.033) 137.268,83.033 137.268,83.405 cw(c137.359,83.405) 137.449,83.405 137.449,83.033 ccw(c137.54,83.033) 137.631,83.033 137.631,83.405 cw(c137.722,83.405) 137.813,83.405 137.813,83.339 ccw(c137.974,83.34) 137.994,83.18 138.04,83.226 138.12,83.306 138.254,83.44 141.504,83.44 141.781,83.163 142.087,83.163 v1(142.461,82.789)
DDR_CH0_DM0_A: U3.Y4 U15.C3 | length 13.2
  Top Layer 1 _Signal w0.203: U15.C3@134.45,77.021 134.478,76.993 134.478,76.852 134.81,76.52 134.81,76.283 134.89,76.203 134.89,75.571 135.388,75.073 136.639,75.073 136.667,75.045 137.447,75.045 139.107,76.706 139.107,77.112 v1(139.145,77.15) ; v1(143.756,77.582) 143.756,77.605 U3.Y4@144.079,77.928
  Bottom Layer_Signals w0.203: v1(139.145,77.15) 139.948,77.953 140.089,77.953 140.591,78.455 142.884,78.455 v1(143.756,77.582)
DDR_CH0_DM0_B: U3.G4 U15.Y3 | length 14
  Top Layer 1 _Signal w0.203: U15.Y3@134.45,88.071 134.81,88.431 134.81,89.199 134.826,89.215 134.826,90.018 134.786,90.058 v1(134.786,90.603) ; v1(143.804,86.616) 143.823,86.616 144.061,86.378 U3.G4@144.079,86.378
  L8_Signals w0.135: v1(134.786,90.603) 136.881,90.603 136.904,90.626 139.253,90.626 140.958,88.921 141.216,88.921 141.501,88.637 141.501,88.612 141.58,88.533 142.119,88.533 142.674,87.978 142.857,87.978 143.412,87.423 143.412,87.008 v1(143.804,86.616)
DDR_CH0_DM1_A: U3.AB4 U15.C10 | length 20.8
  Top Layer 1 _Signal w0.203: U15.C10@128.85,77.021 128.878,76.993 128.982,76.993 v1(129.303,76.671) ; U3.AB4@144.079,76.628 144.079,76.619 144.399,76.3 v1(144.399,76.291)
  Bottom Layer_Signals w0.203: v1(129.303,76.671) 129.303,76.082 129.85,75.535 129.85,74.999 129.647,74.796 129.647,74.628 129.798,74.477 129.798,74.157 129.786,74.145 129.786,73.977 130.99,72.773 140.967,72.773 142.767,74.573 142.767,74.59 143.57,75.393 143.57,75.58 143.883,75.893 143.923,75.893 144.222,76.192 144.247,76.192 144.345,76.291 v1(144.399,76.291)
DDR_CH0_DM1_B: U3.E4 U15.Y10 | length 20.7
  Top Layer 1 _Signal w0.203: U15.Y10@128.85,88.071 128.49,88.431 128.49,89.888 128.526,89.925 128.526,90.14 129.071,90.685 129.392,90.685 129.509,90.569 129.763,90.569 v1(129.801,90.531) ; U3.E4@144.079,87.678 144.079,87.691 144.357,87.969 v1(144.357,87.982)
  L8_Signals w0.135: v1(129.801,90.531) 130.65,91.38 141.206,91.38 142.754,89.832 142.754,89.819 142.96,89.613 142.973,89.613 143.405,89.181 143.405,89.113 143.611,88.907 143.679,88.907 144.025,88.561 144.025,88.471 144.053,88.443 144.053,88.286 v1(144.357,87.982)
DDR_CH0_DQ0_A: U3.U1 U15.B2 | length 13.5
  Top Layer 1 _Signal w0.203: U15.B2@135.25,76.371 135.69,75.931 135.69,75.809 135.69,75.571 135.901,75.36 136.139,75.36 136.52,75.36 v1(136.743,75.583) ; v1(141.138,79.78) 141.191,79.78 141.289,79.878 U3.U1@142.129,79.878
  L8_Signals w0.135: v1(136.743,75.583) 136.743,75.512 136.953,75.301 136.953,75.231 137.159,75.025 137.621,75.025 138.18,75.583 138.276,75.583 138.371,75.679 ccw(c138.275,75.774) 138.371,75.869 138.179,76.061 cw(c138.238,76.119) 138.179,76.178 cw(c138.238,76.119) 138.296,76.178 138.58,75.894 ccw(c138.638,75.952) 138.697,75.894 ccw(c138.638,75.952) 138.697,76.011 138.413,76.295 cw(c138.472,76.353) 138.413,76.412 cw(c138.472,76.353) 138.53,76.412 138.789,76.152 ccw(c138.848,76.211) 138.906,76.152 ccw(c138.848,76.211) 138.906,76.269 138.647,76.528 cw(c138.705,76.587) 138.647,76.645 cw(c138.705,76.587) 138.764,76.645 138.955,76.454 ccw(c139.051,76.549) 139.146,76.454 139.296,76.604 139.456,76.764 139.536,76.764 140.237,77.464 140.237,77.989 141.247,79 141.247,79.299 141.168,79.378 141.168,79.75 v1(141.138,79.78)
DDR_CH0_DQ0_B: U3.H1 U15.AA2 | length 13.1
  Top Layer 1 _Signal w0.203: U15.AA2@135.25,88.721 135.25,88.731 135.644,89.125 v1(135.644,89.135) ; v1(139.956,87.124) 139.969,87.112 139.98,87.112 141.364,85.728 U3.H1@142.129,85.728
  L8_Signals w0.135: v1(135.644,89.135) 137.945,89.135 137.977,89.104 138.025,89.056 ccw(c138.12,89.151) 138.215,89.056 138.322,89.162 cw(c138.378,89.106) 138.435,89.162 cw(c138.378,89.106) 138.435,89.049 137.99,88.604 ccw(c138.046,88.547) 137.99,88.49 ccw(c138.046,88.547) 138.103,88.49 138.548,88.936 cw(c138.605,88.879) 138.662,88.936 cw(c138.605,88.879) 138.662,88.822 138.216,88.377 ccw(c138.273,88.32) 138.216,88.264 ccw(c138.273,88.32) 138.33,88.264 138.775,88.709 cw(c138.832,88.652) 138.888,88.709 cw(c138.832,88.652) 138.888,88.596 138.443,88.15 ccw(c138.5,88.094) 138.443,88.037 ccw(c138.5,88.094) 138.556,88.037 138.743,88.224 cw(c138.8,88.167) 138.857,88.224 cw(c138.8,88.167) 138.857,88.111 138.791,88.045 ccw(c138.847,87.988) 138.791,87.931 ccw(c138.847,87.988) 138.904,87.931 138.931,87.959 cw(c139.027,87.863) 139.122,87.959 139.337,87.743 139.385,87.696 v1(139.956,87.124)
DDR_CH0_DQ1_A: U3.T2 U15.C2 | length 14.5
  Top Layer 1 _Signal w0.203: U15.C2@135.25,77.021 135.29,77.021 135.574,76.736 v1(135.579,76.736) ; v1(142.486,80.211) 142.486,80.222 142.779,80.516 U3.T2@142.779,80.528
  L8_Signals w0.135: v1(135.579,76.736) 136.9,76.736 137.572,77.408 137.733,77.569 cw(c137.828,77.474) 137.924,77.569 138.247,77.246 ccw(c138.304,77.302) 138.36,77.246 ccw(c138.304,77.302) 138.36,77.359 137.887,77.832 cw(c137.944,77.889) 137.887,77.945 cw(c137.944,77.889) 138.001,77.945 138.474,77.472 ccw(c138.53,77.529) 138.587,77.472 ccw(c138.53,77.529) 138.587,77.586 138.114,78.059 cw(c138.171,78.115) 138.114,78.172 cw(c138.171,78.115) 138.227,78.172 138.7,77.699 ccw(c138.757,77.756) 138.814,77.699 ccw(c138.757,77.756) 138.814,77.812 138.443,78.183 cw(c138.5,78.239) 138.443,78.296 cw(c138.5,78.239) 138.557,78.296 138.878,77.974 ccw(c138.935,78.031) 138.992,77.974 ccw(c138.935,78.031) 138.992,78.088 138.717,78.362 cw(c138.812,78.458) 138.717,78.553 139.281,79.117 139.66,79.496 139.66,79.503 140.386,80.229 142.467,80.229 v1(142.486,80.211)
DDR_CH0_DQ1_B: U3.J2 U15.Y2 | length 15.5
  Top Layer 1 _Signal w0.203: U15.Y2@135.25,88.071 135.29,88.071 135.577,88.358 135.688,88.358 v1(135.726,88.396) ; v5@142.485,85.341 142.501,85.341 142.764,85.078 U3.J2@142.779,85.078
  L8_Signals w0.135: v1(135.726,88.396) 136.701,88.396 136.748,88.442 137.039,88.442 137.209,88.271 137.244,88.236 137.334,88.236 137.348,88.222 cw(c137.253,88.127) 137.348,88.031 136.937,87.621 ccw(c136.994,87.564) 136.937,87.507 ccw(c136.994,87.564) 137.051,87.507 137.646,88.102 cw(c137.702,88.046) 137.759,88.102 cw(c137.702,88.046) 137.759,87.989 137.21,87.439 ccw(c137.266,87.383) 137.21,87.326 ccw(c137.266,87.383) 137.323,87.326 137.872,87.876 cw(c137.929,87.819) 137.986,87.876 cw(c137.929,87.819) 137.986,87.762 137.658,87.434 ccw(c137.714,87.378) 137.658,87.321 ccw(c137.714,87.378) 137.771,87.321 137.915,87.465 cw(c138.01,87.369) 138.106,87.465 138.442,87.128 138.442,87.011 138.454,87 139.471,85.983 140.402,85.983 140.79,85.595 140.897,85.488 ccw(c140.992,85.583) 141.127,85.583 141.127,85.897 cw(c141.207,85.897) 141.288,85.897 141.288,85.193 ccw(c141.368,85.193) 141.448,85.193 141.448,85.706 cw(c141.528,85.706) 141.608,85.706 141.608,85.49 ccw(c141.743,85.49) 141.743,85.355 142.06,85.355 142.47,85.355 v5@142.485,85.341
  other v5: 142.509,85.285
DDR_CH0_DQ2_A: U3.T1 U15.E2 | length 13.2
  Top Layer 1 _Signal w0.203: U15.E2@135.25,78.321 135.55,78.021 v1(135.559,78.021) ; v1(139.309,79.641) 139.309,79.646 140.19,80.528 U3.T1@142.129,80.528
  L8_Signals w0.135: v1(135.559,78.021) 136.012,78.021 136.24,78.021 cw(c136.24,77.886) 136.375,77.886 136.375,77.352 ccw(c136.455,77.352) 136.535,77.352 136.535,78.048 cw(c136.615,78.048) 136.696,78.048 136.696,77.352 ccw(c136.776,77.352) 136.856,77.352 136.856,78.048 cw(c136.936,78.048) 137.016,78.048 137.016,77.604 ccw(c137.096,77.604) 137.176,77.604 137.176,77.886 cw(c137.311,77.886) 137.311,78.021 137.634,78.021 137.653,78.021 137.708,78.075 137.755,78.123 ccw(c137.66,78.218) 137.755,78.313 137.748,78.32 cw(c137.805,78.377) 137.748,78.434 cw(c137.805,78.377) 137.862,78.434 137.907,78.388 ccw(c137.964,78.445) 138.021,78.388 ccw(c137.964,78.445) 138.021,78.501 137.975,78.547 cw(c138.032,78.604) 137.975,78.66 cw(c138.032,78.604) 138.088,78.66 138.237,78.512 ccw(c138.293,78.568) 138.35,78.512 ccw(c138.293,78.568) 138.35,78.625 138.202,78.774 cw(c138.258,78.83) 138.202,78.887 cw(c138.258,78.83) 138.315,78.887 138.322,78.88 ccw(c138.417,78.975) 138.513,78.88 138.722,79.089 138.722,79.139 139.117,79.534 139.13,79.534 139.237,79.641 v1(139.309,79.641)
DDR_CH0_DQ2_B: U3.J1 U15.V2 | length 14.7
  Top Layer 1 _Signal w0.203: U15.V2@135.25,86.771 135.29,86.771 135.532,87.013 135.644,87.013 v1(135.681,87.051) ; v1(140.146,85.615) 140.199,85.615 140.298,85.517 140.32,85.517 140.758,85.078 U3.J1@142.129,85.078
  L8_Signals w0.135: v1(135.681,87.051) 136.128,87.051 136.195,87.051 ccw(c136.195,87.186) 136.33,87.186 136.33,87.538 cw(c136.41,87.538) 136.49,87.538 136.49,86.288 ccw(c136.57,86.288) 136.651,86.288 136.651,87.247 cw(c136.731,87.247) 136.811,87.247 136.811,86.288 ccw(c136.891,86.288) 136.971,86.288 136.971,87.035 cw(c137.051,87.035) 137.131,87.035 137.131,86.78 ccw(c137.211,86.78) 137.292,86.78 137.292,86.916 cw(c137.426,86.916) 137.426,87.051 137.668,87.051 137.732,86.986 137.74,86.979 137.74,86.837 137.946,86.631 138.087,86.631 138.359,86.359 138.407,86.311 ccw(c138.502,86.407) 138.598,86.311 138.659,86.372 cw(c138.715,86.316) 138.772,86.372 cw(c138.715,86.316) 138.772,86.259 138.444,85.931 ccw(c138.501,85.874) 138.444,85.818 ccw(c138.501,85.874) 138.557,85.818 138.861,86.121 cw(c138.918,86.065) 138.974,86.121 cw(c138.918,86.065) 138.974,86.008 138.938,85.971 ccw(c139.033,85.876) 138.938,85.781 139.078,85.64 139.103,85.615 139.148,85.615 v1(140.146,85.615)
DDR_CH0_DQ3_A: U3.R2 U15.F2 | length 14.3
  Top Layer 1 _Signal w0.203: U15.F2@135.25,78.971 135.583,78.637 v1(135.603,78.637) ; v1(142.46,80.837) 142.46,80.848 142.76,81.147 142.779,81.147 U3.R2@142.779,81.178
  L8_Signals w0.135: v1(135.603,78.637) 135.894,78.347 137.352,78.347 137.967,78.962 138.015,79.009 ccw(c137.919,79.105) 138.015,79.2 138.002,79.213 cw(c138.059,79.27) 138.002,79.326 cw(c138.059,79.27) 138.115,79.326 138.257,79.185 ccw(c138.314,79.241) 138.37,79.185 ccw(c138.314,79.241) 138.37,79.298 137.976,79.693 cw(c138.032,79.749) 137.976,79.806 cw(c138.032,79.749) 138.089,79.806 138.49,79.405 ccw(c138.547,79.462) 138.603,79.405 ccw(c138.547,79.462) 138.603,79.518 138.202,79.919 cw(c138.259,79.976) 138.202,80.033 cw(c138.259,79.976) 138.316,80.033 138.717,79.632 ccw(c138.773,79.688) 138.83,79.632 ccw(c138.773,79.688) 138.83,79.745 138.429,80.146 cw(c138.486,80.203) 138.429,80.259 cw(c138.486,80.203) 138.542,80.259 138.929,79.872 ccw(c138.986,79.929) 139.043,79.872 ccw(c138.986,79.929) 139.043,79.985 138.714,80.315 cw(c138.77,80.371) 138.714,80.428 cw(c138.77,80.371) 138.827,80.428 139.035,80.22 ccw(c139.13,80.315) 139.226,80.22 139.559,80.553 139.838,80.553 142.171,80.553 142.454,80.837 v1(142.46,80.837)
DDR_CH0_DQ3_B: U3.K2 U15.U2 | length 15.7
  Top Layer 1 _Signal w0.203: U15.U2@135.25,86.121 135.65,85.721 v1(135.65,85.695) v1@135.645,85.695 ; v1(142.51,84.659) 142.516,84.659 142.748,84.428 U3.K2@142.779,84.428
  L8_Signals w0.135: v1(135.65,85.695) 136.273,85.073 137.472,85.073 137.539,85.073 ccw(c137.539,85.208) 137.674,85.208 137.674,85.792 cw(c137.754,85.792) 137.834,85.792 137.834,84.61 ccw(c137.914,84.61) 137.995,84.61 137.995,85.792 cw(c138.075,85.792) 138.155,85.792 138.155,84.61 ccw(c138.235,84.61) 138.315,84.61 138.315,85.495 cw(c138.395,85.495) 138.475,85.495 138.475,84.61 ccw(c138.555,84.61) 138.636,84.61 138.636,85.307 cw(c138.716,85.307) 138.796,85.307 138.796,85.208 ccw(c138.931,85.208) 138.931,85.073 139.699,85.073 140.403,85.073 140.718,84.757 141.964,84.757 142.04,84.682 142.487,84.682 v1(142.51,84.659)
DDR_CH0_DQ4_A: U3.W1 U15.F4 | length 13.2
  Top Layer 1 _Signal w0.203: U15.F4@133.65,78.971 133.91,78.711 v1(133.91,78.701) ; v1(137.594,79.237) 138.253,78.578 138.416,78.578 138.518,78.578 ccw(c138.518,78.781) 138.721,78.781 138.721,78.889 cw(c138.836,78.889) 138.95,78.889 138.95,78.109 ccw(c139.064,78.109) 139.178,78.109 139.178,78.889 cw(c139.293,78.889) 139.407,78.889 139.407,78.109 ccw(c139.521,78.109) 139.636,78.109 139.636,78.795 cw(c139.75,78.795) 139.864,78.795 139.864,78.781 ccw(c140.067,78.781) 140.067,78.578 141.076,78.578 U3.W1@142.129,78.578
  L8_Signals w0.135: v1(133.91,78.701) 134.196,78.988 134.482,78.988 134.483,78.989 135.748,78.989 135.758,78.979 136.271,78.979 136.342,79.049 136.633,79.049 136.703,78.979 137.284,78.979 137.542,79.237 v1(137.594,79.237)
DDR_CH0_DQ4_B: U3.F1 U15.U4 | length 15.4
  Top Layer 1 _Signal w0.203: v1(133.25,86.414) 133.287,86.376 133.355,86.376 133.61,86.121 U15.U4@133.65,86.121 ; v1(140.625,88.469) 140.625,87.904 141.5,87.028 U3.F1@142.129,87.028
  L8_Signals w0.135: v1(133.25,86.414) 133.25,86.461 132.611,87.1 132.611,87.825 132.455,87.98 132.455,89.032 132.875,89.452 133.347,89.452 133.818,89.924 136.829,89.924 ; 136.83,89.923 137.195,89.923 ; 137.195,89.924 137.84,89.924 138.211,90.295 138.905,90.295 140.528,88.672 140.528,88.637 140.625,88.541 v1(140.625,88.469)
DDR_CH0_DQ5_A: U3.V2 U15.E4 | length 15.1
  Top Layer 1 _Signal w0.203: U15.E4@133.65,78.321 v1(133.914,78.057) ; U3.V2@142.779,79.228 v1(143.08,79.529)
  L8_Signals w0.135: v1(133.914,78.057) 133.911,78.054 133.911,77.761 133.615,77.465 133.615,76.559 134.008,76.166 135.663,76.166 137.181,74.649 138.285,74.649 138.387,74.547 138.678,74.547 139.458,75.327 139.458,75.756 141.539,77.837 141.539,78.013 142.104,78.577 142.128,78.577 v1(143.08,79.529)
DDR_CH0_DQ5_B: U3.G2 U15.V4 | length 15.5
  Top Layer 1 _Signal w0.203: v1(133.298,87.074) 133.322,87.074 133.626,86.771 U15.V4@133.65,86.771 ; U3.G2@142.779,86.41 U3.G2@142.779,86.378 v1(143.115,86.714)
  L8_Signals w0.135: v1(133.298,87.074) 133.247,87.125 133.111,87.125 132.829,87.407 132.829,89.097 132.966,89.234 133.437,89.234 133.909,89.705 136.066,89.705 137.931,89.705 138.302,90.076 138.774,90.076 139.114,89.737 139.114,89.598 140.273,88.438 140.273,88.323 141.522,87.075 141.637,87.075 141.902,86.809 142.948,86.809 143.044,86.714 v1(143.115,86.714)
DDR_CH0_DQ6_A: U3.V1 U15.C4 | length 12.1
  Top Layer 1 _Signal w0.203: U15.C4@133.65,77.021 v1(133.966,76.705) ; v1(139.948,79.295) 140.015,79.228 U3.V1@142.129,79.228
  L8_Signals w0.135: v1(133.966,76.705) 134.286,76.385 136.858,76.385 137.22,76.746 137.828,76.746 137.924,76.746 138.019,76.842 137.822,77.039 137.935,77.152 138.39,76.698 138.503,76.811 138.369,76.945 138.482,77.059 138.652,76.889 138.765,77.002 138.595,77.172 138.709,77.285 138.746,77.248 138.859,77.361 138.822,77.399 138.935,77.512 138.973,77.475 139.112,77.613 139.22,77.721 139.242,77.744 139.277,77.778 139.277,78.623 v1(139.948,79.295)
DDR_CH0_DQ6_B: U3.G1 U15.Y4 | length 15.1
  Top Layer 1 _Signal w0.203: v1(133.21,88.372) 133.247,88.334 133.347,88.334 133.61,88.071 U15.Y4@133.65,88.071 ; v1(140.713,87.11) 140.988,86.835 141.445,86.378 141.96,86.378 U3.G1@142.129,86.378
  L8_Signals w0.135: v1(133.21,88.372) 133.164,88.418 133.164,88.799 133.38,89.015 133.528,89.015 133.999,89.486 135.976,89.486 ; 135.976,89.486 138.021,89.486 138.393,89.857 138.684,89.857 138.889,89.652 138.889,89.361 138.807,89.278 138.807,89.099 138.855,89.052 ccw(c138.95,89.147) 139.045,89.052 139.123,89.13 cw(c139.198,89.055) 139.273,89.13 cw(c139.198,89.055) 139.273,88.98 139.17,88.878 ccw(c139.245,88.804) 139.17,88.729 ccw(c139.245,88.804) 139.32,88.729 139.422,88.831 cw(c139.497,88.757) 139.571,88.831 cw(c139.497,88.757) 139.571,88.682 139.214,88.325 ccw(c139.289,88.25) 139.214,88.176 ccw(c139.289,88.25) 139.363,88.176 139.705,88.517 cw(c139.78,88.443) 139.854,88.517 cw(c139.78,88.443) 139.854,88.368 139.601,88.115 ccw(c139.676,88.04) 139.601,87.965 ccw(c139.676,88.04) 139.75,87.965 cw(c139.846,87.87) 139.941,87.965 140.051,87.855 140.099,87.807 140.102,87.805 140.102,87.476 140.307,87.27 140.307,87.25 140.431,87.127 140.696,87.127 v1(140.713,87.11)
DDR_CH0_DQ7_A: U3.U2 U15.B4 | length 15.5
  Top Layer 1 _Signal w0.203: v1(133.239,77.333) 133.23,77.324 133.23,76.79 U15.B4@133.65,76.371 ; v1@142.446,79.591 v1(142.446,79.567) 142.468,79.567 U3.U2@142.779,79.878
  L8_Signals w0.135: v1(133.239,77.333) 133.239,77.404 133.329,77.495 133.329,77.834 133.558,78.063 133.558,78.847 133.68,78.969 133.918,79.206 134.391,79.206 134.392,79.207 135.839,79.207 135.849,79.197 136.181,79.197 136.251,79.268 136.723,79.268 136.794,79.197 137.058,79.197 138.632,80.772 141.415,80.772 141.831,81.188 142.726,81.188 143.102,80.812 143.102,80.222 v1(142.446,79.567)
DDR_CH0_DQ7_B: U3.H2 U15.AA4 | length 15
  Top Layer 1 _Signal w0.203: U15.AA4@133.65,88.721 133.665,88.721 134.016,88.37 v1(134.031,88.37) ; U3.H2@142.779,85.728 143.115,86.064 v5(143.125,86.073)
  L8_Signals w0.135: v1(134.031,88.37) 134.445,88.784 137.387,88.784 138.608,87.563 138.656,87.515 ccw(c138.751,87.611) 138.846,87.515 138.995,87.663 cw(c139.051,87.607) 139.108,87.663 cw(c139.051,87.607) 139.108,87.55 138.718,87.16 ccw(c138.774,87.103) 138.718,87.047 ccw(c138.774,87.103) 138.831,87.047 139.221,87.437 cw(c139.278,87.38) 139.334,87.437 cw(c139.278,87.38) 139.335,87.323 138.944,86.933 ccw(c139,86.876) 138.944,86.819 ccw(c139,86.876) 139.057,86.819 139.435,87.197 cw(c139.492,87.14) 139.548,87.197 cw(c139.492,87.14) 139.548,87.084 139.208,86.744 ccw(c139.265,86.687) 139.208,86.63 ccw(c139.265,86.687) 139.322,86.63 139.336,86.644 cw(c139.431,86.549) 139.526,86.644 139.948,86.223 139.969,86.202 140.021,86.202 142.906,86.202 143.044,86.064 v5@143.115,86.064
DDR_CH0_DQ8_A: U3.AB2 U15.B11 | length 19.8
  Top Layer 1 _Signal w0.203: v1(127.664,76.034) 127.714,76.034 U15.B11@128.05,76.371 ; v1@142.454,76.263 v1(142.454,76.28) 142.454,76.303 U3.AB2@142.779,76.628
  L3_Signals w0.179: v1(127.664,76.034) 127.664,75.616 127.605,75.557 127.605,74.243 129.079,72.769 138.885,72.769 142.397,76.28 v1(142.454,76.28)
DDR_CH0_DQ8_B: U3.D2 U15.AA11 | length 20
  Top Layer 1 _Signal w0.203: U15.AA11@128.05,88.721 127.69,89.081 127.69,89.821 128.159,90.291 v1(128.159,91.065) ; U3.D2@142.779,88.328 142.779,88.339 143.104,88.664 v1(143.104,88.676)
  L3_Signals w0.179: v1(128.159,91.065) 128.159,91.125 128.453,91.419 130.401,91.419 130.437,91.382 130.747,91.382 130.783,91.419 141.266,91.419 142.53,90.155 142.53,89.31 143.104,88.735 v1(143.104,88.676)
